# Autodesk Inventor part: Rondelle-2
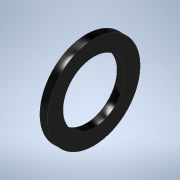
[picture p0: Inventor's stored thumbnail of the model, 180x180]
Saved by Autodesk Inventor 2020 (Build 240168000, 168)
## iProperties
Created: 2023-10
Part Number: Rondelle-2
Material: Générique
Document SubType Name: Modeling
Designer: bruno
Density: 1 g/cm^3
Appearance: Noir
Author: bruno
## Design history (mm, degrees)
sketch "Esquisse1"
  geometry: C1 r 3 at (0, 0); C2 r 2 at (0, 0); 1 further point
  constraints: 2 centre point, 2 coincident
  dimensions: "d0" = 6 diameter of C1; "d1" = 4 diameter of C2
extrude "Extrusion1" new body sketch "Esquisse1" distance "d2" = 0.5; taper "d3" = 0 deg
node "Solide1"
